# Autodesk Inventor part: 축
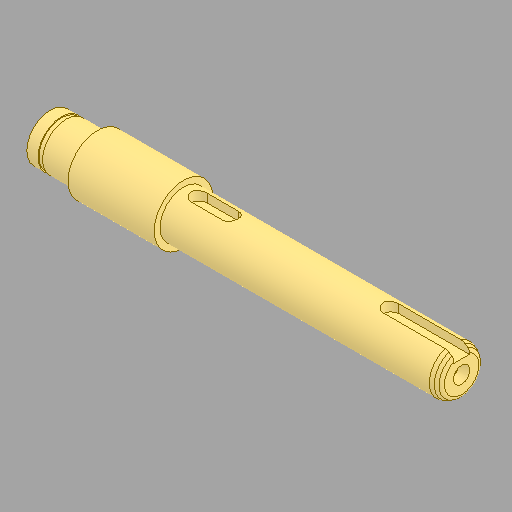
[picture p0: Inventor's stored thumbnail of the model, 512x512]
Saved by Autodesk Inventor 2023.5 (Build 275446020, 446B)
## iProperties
Created: 2026-03
Part Number: 축
Material: 강철, 탄소
Document SubType Name: Modeling
Designer: mirae
Density: 7.85 g/cm^3
Appearance: 기본값
Author: jhkim
Sending System: Autodesk Inventor 2026
Preprocessor: ST-DEVELOPER v20.1
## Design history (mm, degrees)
node "축1"
node "솔리드2"
node "솔리드1"
